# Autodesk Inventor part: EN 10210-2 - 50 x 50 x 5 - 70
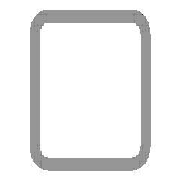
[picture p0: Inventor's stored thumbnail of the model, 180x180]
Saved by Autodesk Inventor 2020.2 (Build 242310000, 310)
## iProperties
IsCustomPart: 1
_CCFamilyMember: 16
_CCFamilyDisplayName: DIN EN 10210-2 (USAS B17.1 quadratisch) - Rohrleitung — In Klammern angegebene Größen wurden aufgehoben
_FrameMemberDoc: Frame Member File
_Version: 15.0.0
_GetPNFromCC: 1
Created: 2019-10
Part Number: EN 10210-2 - 50 x 50 x 5 - 70
Material: Stahl, weich
Description: Rohrleitung
Document SubType Name: Modeling
Standard: DIN
Designer: lutzd
Standard Revision: 2006-07
Standards Organization: DIN
Language: de-DE
Size Designation: 50 x 50 x 5
Categories: <MemberInstance><Categories><Category DisplayName="Profile" InternalName="089c4875-fa83-4c05-b084-43b9cc11f5ed" Mnemonic="GRDR"><CategoryParameter DisplayName="
Stock Number: 50 x 50 x 5
Mass: 479.81 g
Surface Area: 254.441 cm^2
Volume: 61.1222 cm^3
Density: 7.85 g/cm^3
Appearance: Semi-Polished(8)
G_L: 70,000 mm
G_W: 50,000 mm
G_H: 50,000 mm
Dimensions: 50x50x70 mm
Mass: 0,48 kg
DocNumber: ADSK-014294
Folder: .
+94D0A6EA-8974-47FC-8BEB-3596ADA7A1C1+SCHNITTDETAIL1: Schnittwinkel 90,00 grd
VLT_Material: Stahl, weich
Title: Profil-Bauteil
Author: lutzd
Revision Number: -
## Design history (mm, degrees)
node "Startebene"
node "Endebene"
sketch "Skizze"
  geometry: L1 (-25, -17.5)-(-25, 17.5); L2 (-17.5, 25)-(17.5, 25); L3 (25, 17.5)-(25, -17.5); L4 (17.5, -25)-(-17.5, -25); L5 (-15, 20)-(15, 20); L6 (20, 15)-(20, -15); L7 (15, -20)-(-15, -20); L8 (-20, -15)-(-20, 15); L9 (0, 37.175)-(0, -37.175) reference; L10 (-37.175, 0)-(37.175, 0) reference; A1 r 7.5 centre (-17.5, -17.5) between (-25, -17.5) and (-17.5, -25); A2 r 7.5 centre (-17.5, 17.5) between (-17.5, 25) and (-25, 17.5); A3 r 7.5 centre (17.5, 17.5) between (25, 17.5) and (17.5, 25); A4 r 7.5 centre (17.5, -17.5) between (17.5, -25) and (25, -17.5); A5 r 5 centre (-15, -15) between (-20, -15) and (-15, -20); A6 r 5 centre (-15, 15) between (-15, 20) and (-20, 15); A7 r 5 centre (15, 15) between (20, 15) and (15, 20); A8 r 5 centre (15, -15) between (15, -20) and (20, -15)
  constraints: 16 end point, 16 point on circle, 16 tangent, 8 centre point, 6 equal radius, 4 parallel, 2 perpendicular, 2 other
  dimensions: "d7" = 7.5 radius of A1 (= G_IR); "d10" = 50 distance between parallel lines of L2 L4 (= G_H); "d11" = 50 distance between parallel lines of L1 L3 (= G_W); "d12" = 5 distance between parallel lines of L3 L6 (= G_T); "d15" = 25 distance between parallel lines of L2 L10 (= 0.5 x d10); "d16" = 25 distance between parallel lines of L9 L3 (= 0.5 x d11); "d19" = 5 radius of A5 (= G_T); "d20" = 5 distance between parallel lines of L4 L7 (= G_T)
extrude "Körper" new body sketch "Skizze" stored distance "d3" = 70 (= G_L); taper "d4" = 0 deg
node "Driven Length"
  sketch "Sketch3"
    geometry: L1 (0, 0)-(10, 0) reference
    constraints: 2 end point, 1 horizontal
  workplane "Work Plane3"
  sketch "Sketch4"
    geometry: L1 (-2, 25)-(12, 25) reference; L2 (-2, 95)-(12, 95) reference
    dimensions: "d18" = 70 distance between parallel lines of L1 L2 (derived)
workplane "Arbeitsebene4"
feature "Trennen1"
body "Solid1"
other parameters: "G_W" = 50 [user parameter; used in 1 equation term], "G_H" = 50 [user parameter; used in 1 equation term], "G_T" = 5 [user parameter; used in 3 equation terms], "G_IR" = 7.5 [user parameter; used in 1 equation term], "G_L" = 70 (= d18) [user parameter; used in 1 equation term], "G_OFFSET_START" = -25 [user parameter; used in 1 equation term], "G_OFFSET_END" = 0 [user parameter; used in 1 equation term], "d13" = 25 (= -G_OFFSET_START), "d14" = 95 (= G_OFFSET_END + B_L), "B_L" = 95 [user parameter; used in 1 equation term], "d17" = 90 deg
